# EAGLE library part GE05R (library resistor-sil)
SIL RESISTOR
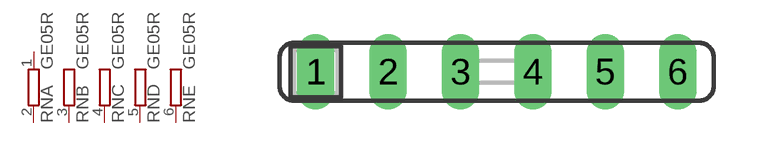
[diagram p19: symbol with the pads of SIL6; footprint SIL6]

Designator prefix RN; gates A=R-NV B=R-NV1 C=R-NV1 D=R-NV1 E=R-NV1

## GE05R (OC_FARNELL: unknown; OC_NEWARK: unknown)  [SIL6]
1  A:1  pas
2  A:2  pas
3  B:2  pas
4  C:2  pas
5  D:2  pas
6  E:2  pas

## Footprint SIL6 (pad centres in mm)
Single In Line
drill 0.813 long: 1 -6.35,0; 2 -3.81,0; 3 -1.27,0; 4 1.27,0; 5 3.81,0; 6 6.35,0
